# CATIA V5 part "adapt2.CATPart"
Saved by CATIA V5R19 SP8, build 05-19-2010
Part number: adapt.1
Bounding box of the stored display mesh (mm): x -20 to 20, y 0 to 71.897, z -20 to 20
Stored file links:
  G:\EU_thinkMotion\CFAO_2010\SIL_groupe1\SIL_groupe1\A reprendre\fbruguiere\fbruguiere\fbruguiere\adapt2.CATPart
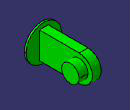
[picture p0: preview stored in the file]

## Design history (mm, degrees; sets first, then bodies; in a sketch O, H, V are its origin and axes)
Body1 (main body)
  Sketch1 on zx-plane, origin (0, 0, 0), H (-1, 0, 0), V (0, 0, 1)
    circle A1 centre (0, 0) radius 5.5
    point P1 (5.5, 0)
    radius A1 = 5.5
    coincidence: A1 P1, P1 H
  Pad1: profile Sketch1, direction (0, 1, 0), length 10
  Sketch2 on end face of Pad1, origin (0, 10, 0), H (-1, 0, 0), V (0, 0, 1)
    circle A1 centre (0, 0) radius 20
    radius A1 = 20
  Pad2: profile Sketch2, direction (0, 1, 0), length 2
  Sketch3 on end face of Pad2, origin (0, 12, 0), H (-1, 0, 0), V (0, 0, 1)
    line L1 (-5, 15) -> (5, 15)
    line L2 (5, 15) -> (5, -15)
    line L3 (5, -15) -> (-5, -15)
    line L4 (-5, -15) -> (-5, 15)
    reference intersected line E1 through (0, 0) direction (-1, 0) from xy-plane
    distance E1 L1 = 15
    distance L3 O = 15
    distance O L2 = 5
    distance L4 O = 5
    horizontal: L1 H, L3 H
    vertical: L2 V, L4 V
  Pad3: profile Sketch3, direction (0, 1, 0), length 60
  Sketch4 on face of Pad3 from Sketch3.L4, origin (5, 0, 0), H (0, 1, 0), V (0, 0, 1)
    arc A1 centre (56.9878, 0) radius 14.9096 from (56.9878, -14.9096) to (56.9878, 14.9096) ccw
    point P1 (56.9878, 0)
    line L1 (56.9878, 21.8345) -> (84.9262, 21.8345)
    line L2 (84.9262, 21.8345) -> (84.9262, -23.7622)
    line L3 (84.9262, -23.7622) -> (56.9878, -23.7622)
    line L4 (56.9878, -23.7622) -> (56.9878, -14.9096)
    line L5 (56.9878, 14.9096) -> (56.9878, 21.8345)
    coincidence: P1 H, L4 L5
    horizontal: L1 H, L3 H
    vertical: L2 V, L4 V, L5 V
  Pocket1: profile Sketch4, direction (-1, 0, 0), length 60
  Sketch5 on face of Pad3 from Sketch3.L4, origin (5, 0, 0), H (0, 1, 0), V (0, 0, 1)
    circle A1 centre (57, 0) radius 10
    point P1 (57, 0)
    reference projected line E1 (12, 15) -> (12, -15) from edge [end face of Pad2 | face of Pad3 from Sketch3.L4]
    radius A1 = 10
    distance P1 E1 = 45
    coincidence: P1 H
  Pad4: profile Sketch5, direction (1, 0, 0), length 10
  Sketch6 on end face of Pad2, origin (0, 12, 0), H (-1, 0, 0), V (0, 0, 1)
